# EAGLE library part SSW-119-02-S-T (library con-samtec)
THROUGH-HOLE .025" SQ POST SOCKET Source: Samtec SSW.pdf
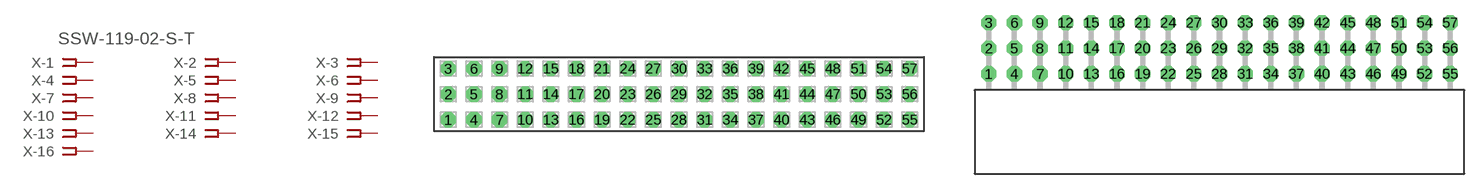
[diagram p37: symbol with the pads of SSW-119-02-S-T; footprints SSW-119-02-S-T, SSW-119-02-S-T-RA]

Designator prefix X; gates -1=FPINV -2=FPIN -3=FPIN -4=FPIN -5=FPIN -6=FPIN -7=FPIN -8=FPIN -9=FPIN -10=FPIN -11=FPIN -12=FPIN -13=FPIN -14=FPIN -15=FPIN -16=FPIN -17=FPIN -18=FPIN -19=FPIN -20=FPIN -21=FPIN -22=FPIN -23=FPIN -24=FPIN -25=FPIN -26=FPIN -27=FPIN -28=FPIN -29=FPIN -30=FPIN -31=FPIN -32=FPIN -33=FPIN -34=FPIN -35=FPIN -36=FPIN -37=FPIN -38=FPIN -39=FPIN -40=FPIN -41=FPIN -42=FPIN -43=FPIN -44=FPIN -45=FPIN -46=FPIN -47=FPIN -48=FPIN -49=FPIN -50=FPIN -51=FPIN -52=FPIN -53=FPIN -54=FPIN -55=FPIN -56=FPIN -57=FPIN

## SSW-119-02-S-T (MPN: SSW-119-02-S-T; OC_FARNELL: unknown; OC_NEWARK: 82P8018)  [SSW-119-02-S-T]
1  -1:1  pas
2  -2:1  pas
3  -3:1  pas
4  -4:1  pas
5  -5:1  pas
6  -6:1  pas
7  -7:1  pas
8  -8:1  pas
9  -9:1  pas
10  -10:1  pas
11  -11:1  pas
12  -12:1  pas
13  -13:1  pas
14  -14:1  pas
15  -15:1  pas
16  -16:1  pas
17  -17:1  pas
18  -18:1  pas
19  -19:1  pas
20  -20:1  pas
21  -21:1  pas
22  -22:1  pas
23  -23:1  pas
24  -24:1  pas
25  -25:1  pas
26  -26:1  pas
27  -27:1  pas
28  -28:1  pas
29  -29:1  pas
30  -30:1  pas
31  -31:1  pas
32  -32:1  pas
33  -33:1  pas
34  -34:1  pas
35  -35:1  pas
36  -36:1  pas
37  -37:1  pas
38  -38:1  pas
39  -39:1  pas
40  -40:1  pas
41  -41:1  pas
42  -42:1  pas
43  -43:1  pas
44  -44:1  pas
45  -45:1  pas
46  -46:1  pas
47  -47:1  pas
48  -48:1  pas
49  -49:1  pas
50  -50:1  pas
51  -51:1  pas
52  -52:1  pas
53  -53:1  pas
54  -54:1  pas
55  -55:1  pas
56  -56:1  pas
57  -57:1  pas

## SSW-119-02-S-TRA (MPN: SSW-119-02-S-T-RA; OC_FARNELL: unknown; OC_NEWARK: 82P8019)  [SSW-119-02-S-T-RA]
Pads as for SSW-119-02-S-T

## Footprint SSW-119-02-S-T (pad centres in mm)
THROUGH-HOLE .025" SQ POST SOCKET Source: Samtec SSW.pdf
drill 1 pad 1.5 octagon: 1 -22.86,-2.54; 2 -22.86,0; 3 -22.86,2.54; 4 -20.32,-2.54; 5 -20.32,0; 6 -20.32,2.54; 7 -17.78,-2.54; 8 -17.78,0; 9 -17.78,2.54; 10 -15.24,-2.54; 11 -15.24,0; 12 -15.24,2.54; 13 -12.7,-2.54; 14 -12.7,0; 15 -12.7,2.54; 16 -10.16,-2.54; 17 -10.16,0; 18 -10.16,2.54; 19 -7.62,-2.54; 20 -7.62,0; 21 -7.62,2.54; 22 -5.08,-2.54; 23 -5.08,0; 24 -5.08,2.54; 25 -2.54,-2.54; 26 -2.54,0; 27 -2.54,2.54; 28 0,-2.54; 29 0,0; 30 0,2.54; 31 2.54,-2.54; 32 2.54,0; 33 2.54,2.54; 34 5.08,-2.54; 35 5.08,0; 36 5.08,2.54; 37 7.62,-2.54; 38 7.62,0; 39 7.62,2.54; 40 10.16,-2.54; 41 10.16,0; 42 10.16,2.54; 43 12.7,-2.54; 44 12.7,0; 45 12.7,2.54; 46 15.24,-2.54; 47 15.24,0; 48 15.24,2.54; 49 17.78,-2.54; 50 17.78,0; 51 17.78,2.54; 52 20.32,-2.54; 53 20.32,0; 54 20.32,2.54; 55 22.86,-2.54; 56 22.86,0; 57 22.86,2.54

## Footprint SSW-119-02-S-T-RA (pad centres in mm)
THROUGH-HOLE .025" SQ POST SOCKET Source: Samtec SSW.pdf
drill 1 pad 1.5 octagon: 1 -22.86,1.524; 2 -22.86,4.064; 3 -22.86,6.604; 4 -20.32,1.524; 5 -20.32,4.064; 6 -20.32,6.604; 7 -17.78,1.524; 8 -17.78,4.064; 9 -17.78,6.604; 10 -15.24,1.524; 11 -15.24,4.064; 12 -15.24,6.604; 13 -12.7,1.524; 14 -12.7,4.064; 15 -12.7,6.604; 16 -10.16,1.524; 17 -10.16,4.064; 18 -10.16,6.604; 19 -7.62,1.524; 20 -7.62,4.064; 21 -7.62,6.604; 22 -5.08,1.524; 23 -5.08,4.064; 24 -5.08,6.604; 25 -2.54,1.524; 26 -2.54,4.064; 27 -2.54,6.604; 28 0,1.524; 29 0,4.064; 30 0,6.604; 31 2.54,1.524; 32 2.54,4.064; 33 2.54,6.604; 34 5.08,1.524; 35 5.08,4.064; 36 5.08,6.604; 37 7.62,1.524; 38 7.62,4.064; 39 7.62,6.604; 40 10.16,1.524; 41 10.16,4.064; 42 10.16,6.604; 43 12.7,1.524; 44 12.7,4.064; 45 12.7,6.604; 46 15.24,1.524; 47 15.24,4.064; 48 15.24,6.604; 49 17.78,1.524; 50 17.78,4.064; 51 17.78,6.604; 52 20.32,1.524; 53 20.32,4.064; 54 20.32,6.604; 55 22.86,1.524; 56 22.86,4.064; 57 22.86,6.604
